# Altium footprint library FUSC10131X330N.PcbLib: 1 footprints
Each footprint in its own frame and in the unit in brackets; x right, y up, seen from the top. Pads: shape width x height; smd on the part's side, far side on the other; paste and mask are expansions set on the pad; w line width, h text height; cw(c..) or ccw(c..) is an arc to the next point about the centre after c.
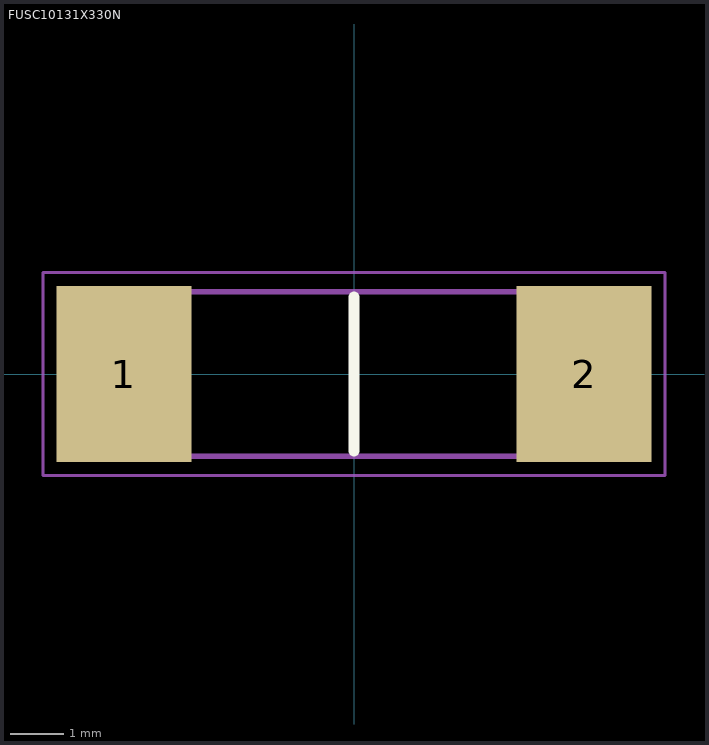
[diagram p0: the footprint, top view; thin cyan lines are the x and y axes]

## FUSC10131X330N [mm]
pads (2):
  rect 2.55x3.32 smd: 1(-4.33,0) 2(4.33,0)
Top Overlay:
  lines w0.2: 0,-1.45 0,1.45
Mechanical 15:
  lines w0.1: -5.05,-1.55 5.05,-1.55 5.05,1.55 -5.05,1.55 -5.05,-1.55
Mechanical 20:
  lines w0.05: -5.855,-1.91 5.855,-1.91 5.855,1.91 -5.855,1.91 -5.855,-1.91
